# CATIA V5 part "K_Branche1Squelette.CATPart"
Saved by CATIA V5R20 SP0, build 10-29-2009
Part number: Branche1(Squelette)
Publications: "Epaisseur_Branche", "Plan.1", "Pivot_Vérin_Branche1", "Point.2", "Droite.1", "Droite.2", "Droite.3"
Bounding box of the stored display mesh (mm): x 12.5 to 27.5, y 160 to 200, z 0 to 10
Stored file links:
  G:\Khaled_CFAO_2011\SIL\SIL_GR1\mneves\Khaled\CAD_CATIA_Modifie\K_Branche1Squelette.CATPart
  G:\Khaled_CFAO_2011\SIL\SIL_GR1\mneves\Khaled\CAD_CATIA_Modifie\K_SquePince_A_Bois.CATProduct
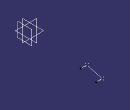
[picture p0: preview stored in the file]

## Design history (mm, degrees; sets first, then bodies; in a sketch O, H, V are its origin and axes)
External parameters (linked from other documents)
  External.Epaisseur_Branche = 15 mm
Set1
  Plane1: linked copy from another document
  Point1 "Pivot_Vérin_Branche1": linked copy from another document
  Point2: linked copy from another document
Set2
  Line1: type PtPt, FirstPoint Point1, SecondPoint Point2
  Line2: type Normal, RefPoint Point1, RefSkin Plane1, Start 0, End 15 {= External.Epaisseur_Branche}
  Line3: type Normal, RefPoint Point2, RefSkin Plane1, Start 0, End 15 {= External.Epaisseur_Branche}
Body1 (main body)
